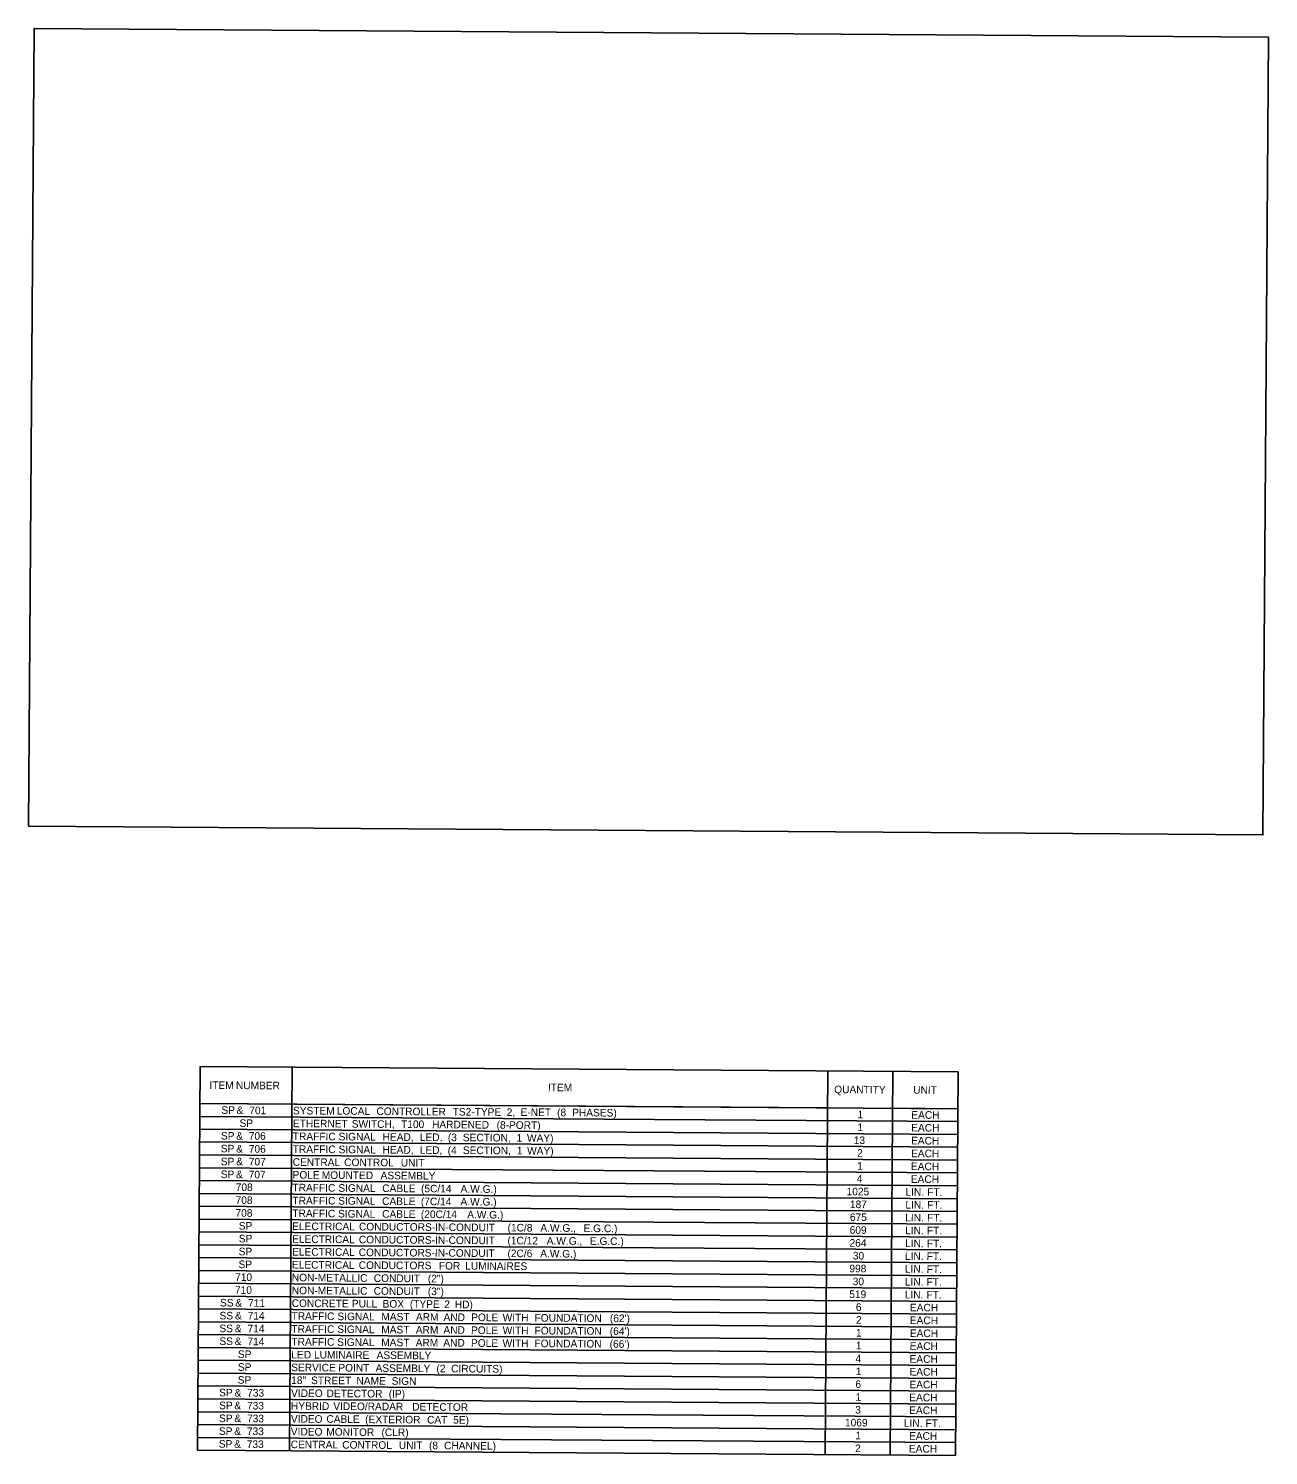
# Model space of a CAD drawing. Extents: x 1802516 to 1809813, y 570772 to 574149.
# Drawn here: x 1805356 to 1806336, y 570772 to 571899 of the extents above; entities that cross this region are included whole.
import ezdxf

# ---------------------------------------------------------------- set-up
doc = ezdxf.new("R2010")
doc.units = 0
for name, color, linetype in [('Default', 7, 'Continuous'), ('MOD_COR', 7, 'Continuous'), ('MOD_Points', 7, 'Continuous')]:
    doc.layers.add(name, color=color, linetype=linetype)

msp = doc.modelspace()

# ---------------------------------------------------------------- linework, layer by layer
at = {"layer": 'Default'}
msp.add_line((1805492.1, 571078.9), (1805492.1, 571078.9), dxfattribs=at)
at = {"layer": 'MOD_COR'}
msp.add_lwpolyline([(1805356.5, 571268.6), (1806331.4, 571261.8), (1806335.8, 571891.8), (1805360.8, 571898.6)], close=True, dxfattribs=at)
at = {"layer": 'MOD_Points'}
for p, q in [((1805490, 570775.9), (1805492.1, 571078.9)), ((1805492.1, 571078.9), (1806090.7, 571074.8)), ((1805562.5, 570775.4), (1805564.6, 571078.4)), ((1805985.7, 570772.5), (1805987.8, 571075.5)), ((1806037.1, 570772.1), (1806039.2, 571075.1)), ((1806088.6, 570771.7), (1806090.7, 571074.8)), ((1805491.9, 571049.7), (1806090.5, 571045.5)), ((1805491.9, 571049.7), (1805987.6, 571046.2)), ((1805491.8, 571039.5), (1806090.5, 571035.4)), ((1806039, 571045.9), (1806090.5, 571045.5)), ((1805491.7, 571029.4), (1806090.4, 571025.2)), ((1805491.7, 571019.3), (1806090.3, 571015.1)), ((1805491.6, 571009.1), (1806090.2, 571005)), ((1805491.5, 570999), (1806090.2, 570994.8)), ((1805491.5, 570988.8), (1806090.1, 570984.7)), ((1805491.4, 570978.7), (1806090, 570974.5)), ((1805491.3, 570968.6), (1806090, 570964.4)), ((1805491.3, 570958.4), (1806089.9, 570954.3)), ((1805491.2, 570948.3), (1806089.8, 570944.1)), ((1805491.1, 570938.1), (1806089.7, 570934)), ((1805491, 570928), (1806089.7, 570923.8)), ((1805491, 570917.9), (1806089.6, 570913.7)), ((1805490.9, 570907.7), (1806089.5, 570903.6)), ((1805490.8, 570897.6), (1806089.5, 570893.4)), ((1805490.8, 570887.4), (1806089.4, 570883.3)), ((1805490.7, 570877.3), (1806089.3, 570873.1)), ((1805490.6, 570867.2), (1806089.3, 570863)), ((1805490.6, 570857), (1806089.2, 570852.9)), ((1805490.5, 570846.9), (1806089.1, 570842.7)), ((1805490.4, 570836.7), (1806089, 570832.6)), ((1805490.3, 570826.6), (1806089, 570822.4)), ((1805490.3, 570816.5), (1806088.9, 570812.3)), ((1805490.2, 570806.3), (1806088.8, 570802.2)), ((1805490.1, 570796.2), (1806088.8, 570792)), ((1805490.1, 570786), (1806088.7, 570781.9)), ((1805490, 570775.9), (1806088.6, 570771.7))]:
    msp.add_line(p, q, dxfattribs=at)

# ---------------------------------------------------------------- texts
at = {"layer": 'Default'}
for s, p in [('ITEM', (1805499.3, 571061.2)), (' NUMBER', (1805518, 571061.1)), ('ITEM', (1805766.7, 571059.4)), ('QUANTITY', (1805992.8, 571057.8)), ('UNIT', (1806055.2, 571057.4)), ('SP', (1805508.8, 571041.5)), (' &', (1805518.6, 571041.4)), ('SP', (1805523.1, 571031.2)), (' 701', (1805528.6, 571041.3)), ('SYSTEM', (1805565.3, 571041.1)), ('ETHERNET', (1805565.3, 571031)), (' LOCAL', (1805597.7, 571040.9)), (' CONTROLLER', (1805629, 571040.6)), (' TS2-TYPE', (1805689.2, 571040.2)), (' 2,', (1805731.9, 571039.9)), (' E-NET', (1805742.9, 571039.9)), (' (8', (1805771.7, 571039.7)), (' PHASES)', (1805783.6, 571039.6)), ('1', (1806011.2, 571038)), ('EACH', (1806053.7, 571037.7)), ('SP', (1805508.4, 571021.2)), (' &', (1805518.2, 571021.1)), (' 706', (1805528.2, 571021.1)), ('TRAFFIC', (1805565.2, 571020.8)), (' SIGNAL', (1805599.1, 571020.6)), (' SWITCH,', (1805609.5, 571030.6)), (' HEAD,', (1805633.9, 571020.3)), (' T100', (1805648.5, 571030.4)), (' LED,', (1805663.3, 571020.1)), (' HARDENED', (1805672.9, 571030.2)), (' (3', (1805685.4, 571020)), (' SECTION,', (1805697.2, 571019.9)), (' (8-PORT)', (1805723.9, 571029.8)), (' WAY)', (1805747.9, 571019.5)), ('1', (1806011.1, 571027.9)), ('EACH', (1806053.6, 571027.6)), ('SP', (1805508.3, 571011.1)), (' &', (1805518.2, 571011)), (' 706', (1805528.2, 571010.9)), ('TRAFFIC', (1805565.1, 571010.7)), (' SIGNAL', (1805599.1, 571010.4)), (' HEAD,', (1805633.8, 571010.2)), (' LED,', (1805663.2, 571010)), (' (4', (1805685.3, 571009.8)), (' SECTION,', (1805697.3, 571009.8)), (' 1', (1805739.7, 571019.6)), (' 1', (1805739.9, 571009.5)), (' WAY)', (1805748, 571009.4)), ('13', (1806008.2, 571017.7)), ('EACH', (1806053.5, 571017.4)), ('SP', (1805508.3, 571000.9)), (' &', (1805518.2, 571000.9)), (' 707', (1805528.2, 571000.8)), ('CENTRAL', (1805565.1, 571000.5)), (' CONTROL', (1805603.5, 571000.3)), (' UNIT', (1805648.2, 571000)), ('2', (1806010.9, 571007.6)), ('1', (1806010.9, 570997.4)), ('EACH', (1806053.4, 570997.1)), ('EACH', (1806053.5, 571007.3)), ('SP', (1805508.2, 570990.8)), (' &', (1805518.1, 570990.7)), (' 707', (1805528.1, 570990.6)), ('POLE', (1805565, 570990.4)), (' MOUNTED', (1805585.8, 570990.2)), (' ASSEMBLY', (1805632.3, 570989.9)), ('4', (1806010.6, 570987.3)), ('EACH', (1806053.3, 570987)), ('708', (1805520.1, 570980.6)), ('TRAFFIC', (1805564.9, 570980.3)), (' SIGNAL', (1805598.9, 570980)), (' CABLE', (1805633.6, 570979.8)), (' (5C/14', (1805664.2, 570979.6)), (' A.W.G.)', (1805695.5, 570979.3)), ('1025', (1806002.6, 570977.2)), ('LIN.', (1806049.1, 570976.9)), (' FT.', (1806064, 570976.8)), ('708', (1805520, 570970.4)), ('TRAFFIC', (1805564.9, 570970.1)), (' SIGNAL', (1805598.8, 570969.9)), (' CABLE', (1805633.5, 570969.6)), (' (7C/14', (1805664.1, 570969.4)), (' A.W.G.)', (1805695.4, 570969.2)), ('187', (1806005.2, 570967.1)), ('LIN.', (1806049, 570966.7)), (' FT.', (1806063.9, 570966.6)), ('708', (1805519.9, 570960.3)), ('TRAFFIC', (1805564.8, 570960)), (' SIGNAL', (1805598.7, 570959.7)), (' CABLE', (1805633.5, 570959.5)), (' (20C/14', (1805664.1, 570959.3)), (' A.W.G.)', (1805700.7, 570959)), ('675', (1806005.2, 570956.9)), ('LIN.', (1806048.9, 570956.6)), (' FT.', (1806063.9, 570956.5)), ('SP', (1805522.5, 570950.1)), ('ELECTRICAL', (1805564.7, 570949.8)), (' CONDUCTORS-IN-CONDUIT', (1805615.2, 570949.5)), (' (1C/8', (1805732.6, 570948.7)), (' A.W.G.,', (1805758.5, 570948.5)), (' E.G.C.)', (1805792.6, 570948.2)), ('609', (1806005, 570946.8)), ('LIN.', (1806048.8, 570946.5)), (' FT.', (1806063.8, 570946.4)), ('SP', (1805522.5, 570940)), ('SP', (1805522.4, 570929.8)), ('ELECTRICAL', (1805564.6, 570929.6)), ('ELECTRICAL', (1805564.6, 570939.7)), (' CONDUCTORS-IN-CONDUIT', (1805615.1, 570939.3)), (' (1C/12', (1805732.5, 570938.5)), (' A.W.G.,', (1805763.5, 570938.3)), (' E.G.C.)', (1805797.6, 570938.1)), ('264', (1806004.9, 570936.6)), ('LIN.', (1806048.8, 570936.3)), (' FT.', (1806063.7, 570936.2)), ('SP', (1805522.3, 570919.7)), ('ELECTRICAL', (1805564.5, 570919.4)), (' CONDUCTORS', (1805615, 570919.1)), (' CONDUCTORS-IN-CONDUIT', (1805615, 570929.2)), (' FOR', (1805678.3, 570918.6)), (' LUMINAIRES', (1805699.1, 570918.5)), (' (2C/6', (1805732.5, 570928.4)), (' A.W.G.)', (1805758.4, 570928.2)), ('30', (1806007.5, 570926.5)), ('LIN.', (1806048.7, 570926.2)), (' FT.', (1806063.6, 570926.1)), ('710', (1805519.6, 570909.6)), ('NON-METALLIC', (1805564.4, 570909.3)), (' CONDUIT', (1805626.9, 570908.8)), (' (2")', (1805669.6, 570908.5)), ('998', (1806004.8, 570916.4)), ('LIN.', (1806048.6, 570916.1)), (' FT.', (1806063.6, 570915.9)), ('710', (1805519.5, 570899.4)), ('NON-METALLIC', (1805564.4, 570899.1)), (' CONDUIT', (1805626.8, 570898.7)), (' (3")', (1805669.6, 570898.4)), ('519', (1806004.7, 570896.1)), ('30', (1806007.4, 570906.2)), ('LIN.', (1806048.6, 570905.9)), ('LIN.', (1806048.5, 570895.8)), (' FT.', (1806063.5, 570905.8)), ('SS', (1805507.7, 570889.4)), (' &', (1805517.6, 570889.3)), (' 711', (1805527.6, 570889.2)), ('CONCRETE', (1805564.3, 570889)), (' PULL', (1805609.6, 570888.7)), (' BOX', (1805633.9, 570888.5)), (' (TYPE', (1805655.4, 570888.4)), (' 2', (1805682.6, 570888.2)), (' HD)', (1805690.9, 570888.1)), ('6', (1806009.9, 570885.9)), ('EACH', (1806052.6, 570885.6)), (' FT.', (1806063.4, 570895.7)), ('SS', (1805507.3, 570879.2)), (' &', (1805517.3, 570879.2)), (' 714', (1805527.3, 570879.1)), ('TRAFFIC', (1805564.2, 570878.9)), (' SIGNAL', (1805598.2, 570878.6)), (' MAST', (1805632.9, 570878.4)), (' ARM', (1805660.2, 570878.2)), (' AND', (1805682, 570878)), (' POLE', (1805703.8, 570877.9)), (' WITH', (1805728.7, 570877.7)), (' FOUNDATION', (1805753.9, 570877.5)), (" (62')", (1805813.4, 570877.1)), ('2', (1806010, 570875.8)), ('EACH', (1806052.5, 570875.5)), ('SS', (1805507.2, 570869.1)), (' &', (1805517.2, 570869)), (' 714', (1805527.2, 570869)), ('TRAFFIC', (1805564.1, 570868.7)), (' SIGNAL', (1805598.1, 570868.5)), (' MAST', (1805632.8, 570868.2)), (' ARM', (1805660.1, 570868)), (' AND', (1805681.9, 570867.9)), (' POLE', (1805703.7, 570867.7)), (' WITH', (1805728.7, 570867.6)), (' FOUNDATION', (1805753.9, 570867.4)), (" (64')", (1805813.3, 570867)), ('1', (1806010, 570865.6)), ('EACH', (1806052.5, 570865.3)), ('SS', (1805507.2, 570859)), (' &', (1805517.1, 570858.9)), (' 714', (1805527.1, 570858.8)), ('TRAFFIC', (1805564.1, 570858.6)), (' SIGNAL', (1805598, 570858.3)), (' MAST', (1805632.8, 570858.1)), (' ARM', (1805660, 570857.9)), (' AND', (1805681.8, 570857.8)), (' POLE', (1805703.7, 570857.6)), (' WITH', (1805728.6, 570857.4)), (' FOUNDATION', (1805753.8, 570857.3)), (" (66')", (1805813.2, 570856.8)), ('1', (1806009.9, 570855.5)), ('EACH', (1806052.4, 570855.2)), ('SP', (1805521.8, 570848.7)), ('LED', (1805564, 570848.4)), (' LUMINAIRE', (1805579.7, 570848.3)), (' ASSEMBLY', (1805629.1, 570848)), ('4', (1806009.6, 570845.3)), ('EACH', (1806052.3, 570845)), ('SP', (1805521.8, 570838.6)), ('SP', (1805521.7, 570828.4)), ('SERVICE', (1805563.9, 570838.3)), ('18"', (1805563.9, 570828.2)), (' STREET', (1805577.4, 570828.1)), (' POINT', (1805598.9, 570838.1)), (' ASSEMBLY', (1805628.3, 570837.8)), (' (2', (1805676.4, 570837.5)), (' CIRCUITS)', (1805688, 570837.4)), ('1', (1806009.8, 570835.2)), ('EACH', (1806052.3, 570834.9)), ('SP', (1805507, 570818.4)), (' &', (1805516.9, 570818.3)), (' 733', (1805526.9, 570818.3)), ('VIDEO', (1805563.8, 570818)), (' DETECTOR', (1805589.6, 570817.8)), (' NAME', (1805613.2, 570827.8)), (' (IP)', (1805638.7, 570817.5)), (' SIGN', (1805641, 570827.6)), ('6', (1806009.5, 570825.1)), ('EACH', (1806052.2, 570824.8)), ('SP', (1805507, 570808.3)), (' &', (1805516.8, 570808.2)), (' 733', (1805526.8, 570808.1)), ('HYBRID', (1805563.7, 570807.9)), (' VIDEO/RADAR', (1805594.9, 570807.7)), (' DETECTOR', (1805657.3, 570807.2)), ('1', (1806009.7, 570814.9)), ('EACH', (1806052.1, 570814.6)), ('SP', (1805506.9, 570798.1)), (' &', (1805516.8, 570798.1)), (' 733', (1805526.8, 570798)), ('VIDEO', (1805563.7, 570797.7)), (' CABLE', (1805589.5, 570797.6)), (' (EXTERIOR', (1805620.1, 570797.3)), (' CAT', (1805669, 570797)), (' 5E)', (1805689.6, 570796.9)), ('1069', (1806001.3, 570794.7)), ('3', (1806009.4, 570804.8)), ('LIN.', (1806047.8, 570794.4)), ('EACH', (1806052, 570804.5)), ('SP', (1805506.8, 570788)), (' &', (1805516.7, 570787.9)), (' 733', (1805526.7, 570787.9)), ('VIDEO', (1805563.6, 570787.6)), (' MONITOR', (1805589.4, 570787.4)), (' (CLR)', (1805633, 570787.1)), ('1', (1806009.5, 570784.5)), ('EACH', (1806051.9, 570784.2)), (' FT.', (1806062.7, 570794.3)), ('SP', (1805506.7, 570777.9)), (' &', (1805516.6, 570777.8)), (' 733', (1805526.6, 570777.7)), ('CENTRAL', (1805563.5, 570777.5)), (' CONTROL', (1805602, 570777.2)), (' UNIT', (1805646.7, 570776.9)), (' (8', (1805670.5, 570776.7)), (' CHANNEL)', (1805682.4, 570776.6)), ('2', (1806009.3, 570774.4)), ('EACH', (1806051.8, 570774.1))]:
    msp.add_text(s, height=6, rotation=359.6021, dxfattribs=at).set_placement(p)

doc.saveas('drawing.dxf')
